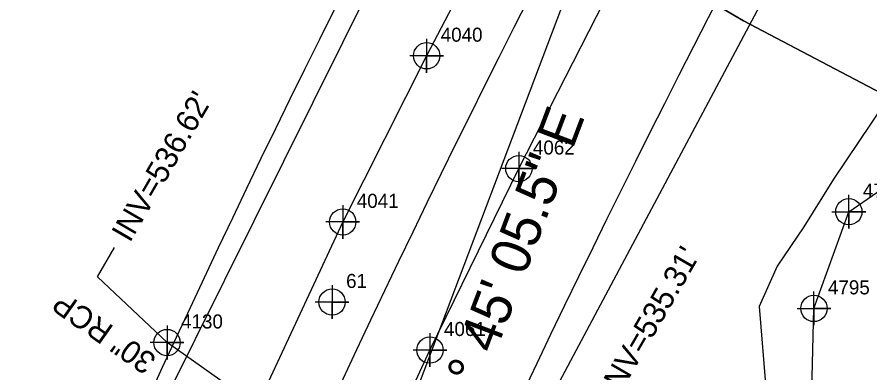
# Model space of a CAD drawing. Extents: x 1653123 to 1656194, y 596584 to 600233.
# Drawn here: x 1653582.5 to 1653734.2, y 597814.6 to 597877.9 of the extents above; entities that cross this region are included whole.
import ezdxf

# ---------------------------------------------------------------- set-up
doc = ezdxf.new("R2010")
doc.units = 0
for name, color, linetype in [('Default Symbol CELL', 7, 'Continuous'), ('Default Symbol Cogo Number', 7, 'Continuous'), ('Exist Horizontal Alignment', 7, 'Continuous'), ('Exist Horizontal Baseline Alignment', 7, 'Continuous'), ('Exist Horizontal Baseline Alignment Direction Label', 7, 'Continuous'), ('Exist Hydro Jurisdictional Stream or Body of Water', 7, 'Continuous'), ('Exist Hydro Stream or Body of Water Cogo Number', 7, 'Continuous'), ('Exist Right of Way Line', 7, 'Continuous'), ('Exist Roads EOP Cogo Point CELL', 7, 'Continuous'), ('Exist Structure Minor Pipes RCP 30 Inch', 7, 'Continuous'), ('Exist Structure Minor Pipes RCP 30 Inch Cogo Number', 7, 'Continuous'), ('Exist Structure Minor Pipes RCP 30 Inch Cogo Point CELL', 7, 'Continuous'), ('Exist Structure Minor Pipes RCP 30 Inch Invert', 7, 'Continuous'), ('Exist Structure Minor Pipes RCP 30 Inch Text', 7, 'Continuous'), ('Exist Vegetation Woods Line', 7, 'Continuous'), ('Prop Conc Shoulder Berm Gutter', 7, 'Continuous'), ('Prop Guardrail', 7, 'Continuous'), ('Prop Guardrail Anchor Unit CELL', 7, 'Continuous'), ('Prop Horizontal Alignment', 7, 'Continuous')]:
    doc.layers.add(name, color=color, linetype=linetype)

msp = doc.modelspace()

# ---------------------------------------------------------------- linework, layer by layer
at = {"layer": 'Default Symbol CELL'}
msp.add_lwpolyline([(1653638.51, 597830.22), (1653638.51, 597824.22), (1653638.51, 597827.22), (1653641.51, 597827.22), (1653635.51, 597827.22)], dxfattribs=at)
msp.add_lwpolyline([(1653638.51, 597830.22), (1653638.51, 597824.22), (1653638.51, 597827.22), (1653641.51, 597827.22), (1653635.51, 597827.22)], dxfattribs=at)
msp.add_circle((1653638.51, 597827.22), 2.34, dxfattribs=at)
msp.add_circle((1653638.51, 597827.22), 2.34, dxfattribs=at)
at = {"layer": 'Exist Horizontal Alignment'}
msp.add_arc((1655696.35, 596851.16), 2270, 149.9451, 159.30371, dxfattribs=at)
at = {"layer": 'Exist Horizontal Baseline Alignment'}
msp.add_line((1653570.02, 597590.97), (1653732.12, 598018.79), dxfattribs=at)
at = {"layer": 'Exist Hydro Jurisdictional Stream or Body of Water'}
msp.add_lwpolyline([(1653703.81, 597789.23), (1653711.98, 597793.87), (1653718.16, 597799.38), (1653723.66, 597804.09), (1653724.22, 597826.08), (1653730.43, 597843.27), (1653737.9, 597848.38), (1653749, 597867.92), (1653762.46, 597888.24), (1653771.7, 597908), (1653776.11, 597927.83), (1653775.18, 597952.39), (1653772.63, 597974.68), (1653768.36, 597994.45), (1653761.04, 598003.47), (1653757.33, 598006.27), (1653756.65, 598007.49)], dxfattribs=at)
at = {"layer": 'Exist Right of Way Line'}
for radius in [2300, 2240]:
    msp.add_arc((1655696.35, 596851.16), radius, 149.9451, 159.30371, dxfattribs=at)
at = {"layer": 'Exist Roads EOP Cogo Point CELL'}
for points in [[(1653655.34, 597873.98), (1653655.34, 597867.98), (1653655.34, 597870.98), (1653658.34, 597870.98), (1653652.34, 597870.98)], [(1653671.74, 597853.93), (1653671.74, 597847.93), (1653671.74, 597850.93), (1653674.74, 597850.93), (1653668.74, 597850.93)], [(1653640.41, 597844.45), (1653640.41, 597838.45), (1653640.41, 597841.45), (1653643.41, 597841.45), (1653637.41, 597841.45)], [(1653655.92, 597821.68), (1653655.92, 597815.68), (1653655.92, 597818.68), (1653658.92, 597818.68), (1653652.92, 597818.68)]]:
    msp.add_lwpolyline(points, dxfattribs=at)
for centre in [(1653655.34, 597870.98), (1653671.74, 597850.93), (1653640.41, 597841.45), (1653655.92, 597818.68)]:
    msp.add_circle(centre, 2.34, dxfattribs=at)
at = {"layer": 'Exist Structure Minor Pipes RCP 30 Inch'}
msp.add_line((1653659.44, 597784.65), (1653609.16, 597820.02), dxfattribs=at)
at = {"layer": 'Exist Structure Minor Pipes RCP 30 Inch Cogo Point CELL'}
msp.add_lwpolyline([(1653609.16, 597823.02), (1653609.16, 597817.02), (1653609.16, 597820.02), (1653612.16, 597820.02), (1653606.16, 597820.02)], dxfattribs=at)
msp.add_circle((1653609.16, 597820.02), 2.34, dxfattribs=at)
at = {"layer": 'Exist Structure Minor Pipes RCP 30 Inch Invert'}
msp.add_lwpolyline([(1653609.16, 597820.02), (1653596.81, 597831.71), (1653599.81, 597836.9)], dxfattribs=at)
at = {"layer": 'Exist Vegetation Woods Line'}
for points in [[(1653661.33, 597915.51), (1653603.59, 597799.41), (1653583.95, 597763.16), (1653578.44, 597758.17), (1653564.7, 597761.25), (1653536.01, 597770.5), (1653508.63, 597776.57), (1653484.83, 597779.68), (1653482.87, 597781.33), (1653483.43, 597790.56), (1653492.03, 597811.3), (1653503.66, 597836.47), (1653511.56, 597849.92), (1653513.67, 597858.14), (1653513.6, 597868.54), (1653511.35, 597878.91), (1653507.78, 597891.42), (1653504.66, 597919.45), (1653504.85, 597944.49), (1653506.49, 597968.64), (1653509.77, 597999.99)], [(1653743.53, 597872.59), (1653727.72, 597849.07), (1653722.44, 597840.57), (1653717.66, 597833.58), (1653714.51, 597826.4), (1653715.63, 597812.68), (1653715.73, 597807.63), (1653713.11, 597803.16), (1653698.27, 597795.72), (1653684.13, 597803.11), (1653677.18, 597807.18), (1653678.58, 597812.27), (1653717.51, 597885.35)]]:
    msp.add_lwpolyline(points, dxfattribs=at)
at = {"layer": 'Prop Conc Shoulder Berm Gutter'}
for points in [[(1653736.93, 598020.21), (1653736.61, 598019), (1653719.2, 597989.18), (1653700.61, 597956.07), (1653684.64, 597926.74), (1653670.3, 597899.63), (1653655.34, 597870.98), (1653640.41, 597841.45), (1653625.56, 597809.57), (1653616.44, 597790.93), (1653615.55, 597790.14), (1653613.35, 597786.4), (1653606.9, 597772.91), (1653600.39, 597757.83), (1653598.65, 597751.55), (1653587.79, 597725.22), (1653577.73, 597701.58), (1653574.75, 597692.21), (1653558.96, 597651.01), (1653542.08, 597605.71)], [(1653564.52, 597597.65), (1653581.19, 597642.12), (1653595.32, 597679.04), (1653605.24, 597704.17), (1653614.92, 597727.36), (1653625.98, 597753.19), (1653641.03, 597786.45), (1653655.92, 597818.68), (1653671.74, 597850.93), (1653688.35, 597883.45), (1653707.13, 597918.97), (1653720.66, 597943.73), (1653734.86, 597970.07), (1653749.84, 597996.36), (1653750.81, 597997.29)]]:
    msp.add_lwpolyline(points, dxfattribs=at)
at = {"layer": 'Prop Guardrail'}
for points in [[(1653903.59, 597776.41), (1653711.71, 597877.2), (1653696.02, 597886.41), (1653672.02, 597900.5), (1653657.82, 597908.84), (1653581.92, 597953.42), (1653467.13, 598020.82), (1653530, 598138.71), (1653544.59, 598164.59), (1653608.47, 598270), (1653650, 598338.52), (1653727.49, 598470), (1653919.05, 598343.12), (1654024.03, 598279.05), (1654101.16, 598231.66), (1654152.92, 598207.08), (1653974.95, 597910)], [(1653467.13, 598020.82), (1653523.07, 597987.98), (1653581.92, 597953.42), (1653657.82, 597908.84), (1653672.02, 597900.5), (1653696.02, 597886.41), (1653711.71, 597877.2), (1653903.59, 597776.41), (1653848.79, 597671.21), (1653796.49, 597523.51), (1653747.41, 597390), (1653709.73, 597290.27), (1653571.5, 597363.59), (1653527.51, 597387.98), (1653462.99, 597422.58), (1653451.94, 597428.93), (1653267.19, 597532.81), (1653332.24, 597710), (1653352.48, 597767.52), (1653388.58, 597870)]]:
    msp.add_lwpolyline(points, close=True, dxfattribs=at)
at = {"layer": 'Prop Guardrail Anchor Unit CELL'}
for points in [[(1653727.43, 597843.27), (1653733.43, 597843.27), (1653730.43, 597843.27), (1653730.43, 597840.27), (1653730.43, 597846.27)], [(1653721.22, 597826.08), (1653727.22, 597826.08), (1653724.22, 597826.08), (1653724.22, 597823.08), (1653724.22, 597829.08)]]:
    msp.add_lwpolyline(points, dxfattribs=at)
for centre in [(1653730.43, 597843.27), (1653724.22, 597826.08)]:
    msp.add_circle(centre, 2.34, dxfattribs=at)

# ---------------------------------------------------------------- texts
at = {"layer": 'Default Symbol Cogo Number'}
msp.add_text('61', height=2.5, dxfattribs=at).set_placement((1653641.01, 597829.72))
at = {"layer": 'Exist Horizontal Baseline Alignment Direction Label'}
msp.add_text('N 20%%d 45\' 05.5" E', height=7, rotation=69.2485, dxfattribs=at).set_placement((1653658.25, 597793.4))
at = {"layer": 'Exist Hydro Stream or Body of Water Cogo Number'}
for s, p in [('4794', (1653732.93, 597845.77)), ('4795', (1653726.72, 597828.58))]:
    msp.add_text(s, height=2.5, dxfattribs=at).set_placement(p)
at = {"layer": 'Exist Structure Minor Pipes RCP 30 Inch Cogo Number'}
msp.add_text('4130', height=2.5, dxfattribs=at).set_placement((1653611.66, 597822.52))
at = {"layer": 'Exist Structure Minor Pipes RCP 30 Inch Invert'}
for s, p in [("INV=536.62'", (1653602.55, 597837.63)), ("INV=535.31'", (1653689.32, 597810.06))]:
    msp.add_text(s, height=4, rotation=59.9255, dxfattribs=at).set_placement(p)
at = {"layer": 'Exist Structure Minor Pipes RCP 30 Inch Text'}
msp.add_text('30" RCP', height=4, rotation=144.8719, dxfattribs=at).set_placement((1653607.52, 597817.4))
at = {"layer": 'Prop Horizontal Alignment'}
for s, p in [('4040', (1653657.84, 597873.48)), ('4062', (1653674.24, 597853.43)), ('4041', (1653642.91, 597843.95)), ('4061', (1653658.42, 597821.18))]:
    msp.add_text(s, height=2.5, dxfattribs=at).set_placement(p)

doc.saveas('drawing.dxf')
